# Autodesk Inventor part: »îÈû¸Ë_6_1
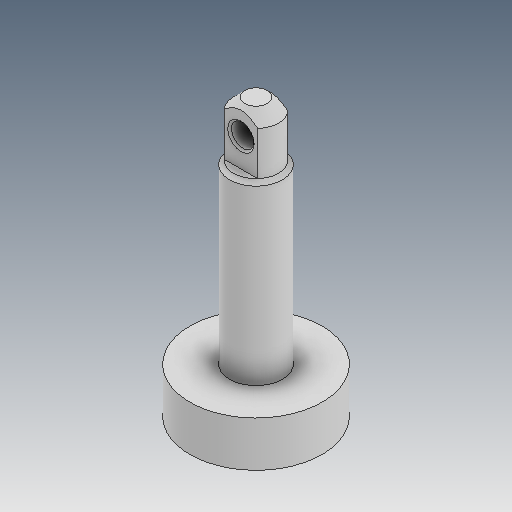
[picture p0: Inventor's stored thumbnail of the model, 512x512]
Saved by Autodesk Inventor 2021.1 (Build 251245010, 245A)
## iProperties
Created: 2019-04
Part Number: »îÈû¸Ë_6_1
Material: Ogólny
Document SubType Name: Modeling
Designer: user
Density: 1 g/cm^3
Appearance: Domyślna
Author: user
Revision Number: ÈÎºÎ
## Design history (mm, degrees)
feature "ÊäÈë1"
node "Bryła1"
